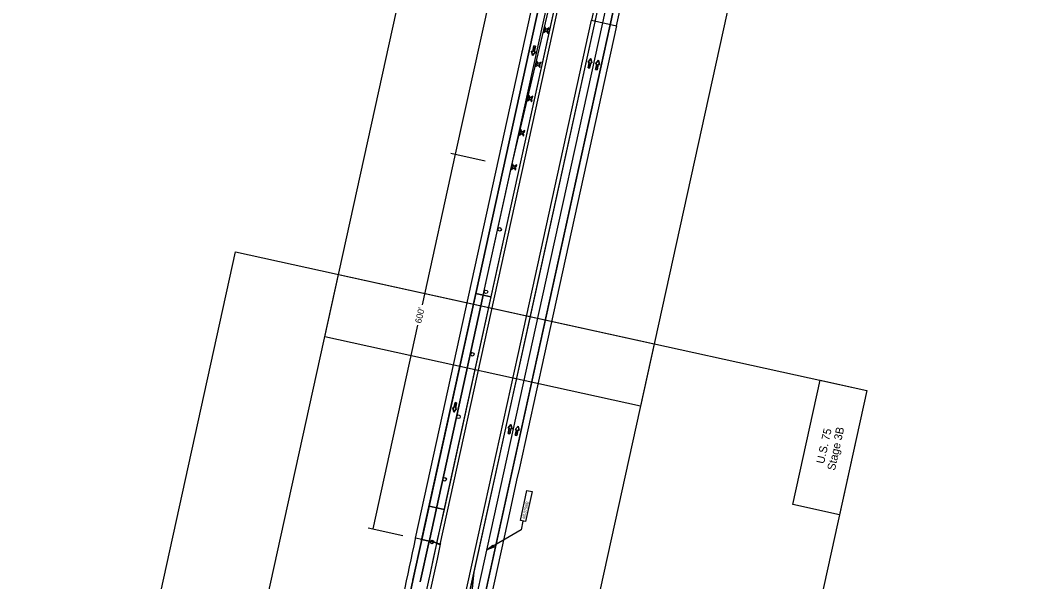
# Model space of a CAD drawing. Extents: x 14104283 to 14121738, y 8635219 to 8671666.
# Drawn here: x 14107490 to 14109077, y 8640895 to 8641773 of the extents above; entities that cross this region are included whole.
import ezdxf

# ---------------------------------------------------------------- set-up
doc = ezdxf.new("R2010")
doc.units = 0
for name, color, linetype in [('Cell', 7, 'Continuous'), ('Default', 7, 'Continuous'), ('dsnNonPlotable', 7, 'Continuous'), ('dsnPaintExistingBrokenLaneLineWhite', 7, 'Continuous'), ('dsnPaintExistingEdgeLineLeftYellow', 7, 'Continuous'), ('dsnPaintExistingEdgeLineRightWhite', 7, 'Continuous'), ('dsnPaintPlaceEdgeLineLeftYellow', 7, 'Continuous'), ('dsnStdLabel', 7, 'Continuous'), ('dsnStgShadingPrevPav', 7, 'Continuous'), ('dsnTapeExistingChannelizingLaneYellow', 7, 'Continuous'), ('dsnTapeRemoveChannelizingYellow', 7, 'Continuous'), ('dsnTextOverlapOdd', 7, 'Continuous'), ('Text', 7, 'Continuous')]:
    doc.layers.add(name, color=color, linetype=linetype)

msp = doc.modelspace()

# ---------------------------------------------------------------- linework, layer by layer
at = {"layer": 'Cell'}
for p, q in [((14108311.3, 8641758.1), (14108308.7, 8641756.9)), ((14108310.2, 8641763), (14108309.6, 8641760.3)), ((14108309.6, 8641760.3), (14108311.3, 8641758.1)), ((14108312.7, 8641758.9), (14108310.2, 8641763)), ((14108316.8, 8641761.4), (14108312.7, 8641758.9)), ((14108313.5, 8641757.6), (14108316.1, 8641758.7)), ((14108315.3, 8641755.3), (14108313.5, 8641757.6)), ((14108316.1, 8641758.7), (14108316.8, 8641761.4)), ((14108308.7, 8641756.9), (14108308.1, 8641754.3)), ((14108308.1, 8641754.3), (14108312.2, 8641756.7)), ((14108312.2, 8641756.7), (14108314.7, 8641752.7)), ((14108314.7, 8641752.7), (14108315.3, 8641755.3)), ((14108297.6, 8641709.5), (14108296.9, 8641706.8)), ((14108300.1, 8641705.4), (14108297.6, 8641709.5)), ((14108296.1, 8641703.4), (14108295.5, 8641700.7)), ((14108295.5, 8641700.7), (14108299.5, 8641703.2)), ((14108298.7, 8641704.6), (14108296.1, 8641703.4)), ((14108296.9, 8641706.8), (14108298.7, 8641704.6)), ((14108299.5, 8641703.2), (14108302, 8641699.1)), ((14108304.1, 8641707.9), (14108300.1, 8641705.4)), ((14108300.9, 8641704), (14108303.5, 8641705.2)), ((14108302.7, 8641701.8), (14108300.9, 8641704)), ((14108302, 8641699.1), (14108302.7, 8641701.8)), ((14108303.5, 8641705.2), (14108304.1, 8641707.9)), ((14108283.5, 8641649.9), (14108282.8, 8641647.2)), ((14108282.8, 8641647.2), (14108286.9, 8641649.7)), ((14108286.1, 8641651), (14108283.5, 8641649.9)), ((14108284.9, 8641655.9), (14108284.3, 8641653.3)), ((14108284.3, 8641653.3), (14108286.1, 8641651)), ((14108287.4, 8641651.9), (14108284.9, 8641655.9)), ((14108286.9, 8641649.7), (14108289.4, 8641645.6)), ((14108291.5, 8641654.4), (14108287.4, 8641651.9)), ((14108288.3, 8641650.5), (14108290.9, 8641651.7)), ((14108290, 8641648.3), (14108288.3, 8641650.5)), ((14108289.4, 8641645.6), (14108290, 8641648.3)), ((14108290.9, 8641651.7), (14108291.5, 8641654.4)), ((14108272.3, 8641602.4), (14108271.7, 8641599.7)), ((14108271.7, 8641599.7), (14108273.4, 8641597.5)), ((14108274.8, 8641598.3), (14108272.3, 8641602.4)), ((14108278.9, 8641600.8), (14108274.8, 8641598.3)), ((14108278.2, 8641598.2), (14108278.9, 8641600.8)), ((14108270.8, 8641596.3), (14108270.2, 8641593.7)), ((14108270.2, 8641593.7), (14108274.3, 8641596.2)), ((14108273.4, 8641597.5), (14108270.8, 8641596.3)), ((14108274.3, 8641596.2), (14108276.7, 8641592.1)), ((14108275.6, 8641597), (14108278.2, 8641598.2)), ((14108277.4, 8641594.8), (14108275.6, 8641597)), ((14108276.7, 8641592.1), (14108277.4, 8641594.8)), ((14108258.2, 8641542.8), (14108257.5, 8641540.1)), ((14108257.5, 8641540.1), (14108261.6, 8641542.6)), ((14108260.8, 8641544), (14108258.2, 8641542.8)), ((14108259.7, 8641548.9), (14108259, 8641546.2)), ((14108259, 8641546.2), (14108260.8, 8641544)), ((14108262.2, 8641544.8), (14108259.7, 8641548.9)), ((14108261.6, 8641542.6), (14108264.1, 8641538.6)), ((14108266.2, 8641547.3), (14108262.2, 8641544.8)), ((14108263, 8641543.5), (14108265.6, 8641544.6)), ((14108264.8, 8641541.2), (14108263, 8641543.5)), ((14108264.1, 8641538.6), (14108264.8, 8641541.2)), ((14108265.6, 8641544.6), (14108266.2, 8641547.3))]:
    msp.add_line(p, q, dxfattribs=at)
for points in [[(14108293, 8641733.2), (14108295.4, 8641732.6), (14108293.6, 8641724.1), (14108295.4, 8641723.7), (14108291, 8641718.2), (14108289.3, 8641725), (14108291.1, 8641724.6)], [(14108380, 8641698.3), (14108377.6, 8641698.8), (14108379.4, 8641707.3), (14108377.6, 8641707.7), (14108382, 8641713.2), (14108383.7, 8641706.4), (14108381.9, 8641706.8)], [(14108391.7, 8641695.7), (14108389.2, 8641696.2), (14108391.1, 8641704.8), (14108389.3, 8641705.2), (14108393.7, 8641710.6), (14108395.4, 8641703.9), (14108393.5, 8641704.3)], [(14108169.8, 8641175.5), (14108172.2, 8641175), (14108170.3, 8641166.4), (14108172.2, 8641166), (14108167.8, 8641160.6), (14108166.1, 8641167.4), (14108167.9, 8641167)], [(14108255.1, 8641126.4), (14108252.6, 8641126.9), (14108254.5, 8641135.4), (14108252.7, 8641135.8), (14108257, 8641141.3), (14108258.8, 8641134.5), (14108256.9, 8641134.9)], [(14108266.2, 8641123.9), (14108263.7, 8641124.4), (14108265.6, 8641133), (14108263.8, 8641133.4), (14108268.2, 8641138.8), (14108269.9, 8641132.1), (14108268, 8641132.5)]]:
    msp.add_lwpolyline(points, close=True, dxfattribs=at)
for points in [[(14108291.1, 8641724.6), (14108289.3, 8641725), (14108291, 8641718.2), (14108295.4, 8641723.7), (14108293.6, 8641724.1), (14108295.4, 8641732.6), (14108293, 8641733.2), (14108291.1, 8641724.6)], [(14108381.9, 8641706.8), (14108383.7, 8641706.4), (14108382, 8641713.2), (14108377.6, 8641707.7), (14108379.4, 8641707.3), (14108377.6, 8641698.8), (14108380, 8641698.3), (14108381.9, 8641706.8)], [(14108393.5, 8641704.3), (14108395.4, 8641703.9), (14108393.7, 8641710.6), (14108389.3, 8641705.2), (14108391.1, 8641704.8), (14108389.2, 8641696.2), (14108391.7, 8641695.7), (14108393.5, 8641704.3)], [(14108167.9, 8641167), (14108166.1, 8641167.4), (14108167.8, 8641160.6), (14108172.2, 8641166), (14108170.3, 8641166.4), (14108172.2, 8641175), (14108169.8, 8641175.5), (14108167.9, 8641167)], [(14108256.9, 8641134.9), (14108258.8, 8641134.5), (14108257, 8641141.3), (14108252.7, 8641135.8), (14108254.5, 8641135.4), (14108252.6, 8641126.9), (14108255.1, 8641126.4), (14108256.9, 8641134.9)], [(14108268, 8641132.5), (14108269.9, 8641132.1), (14108268.2, 8641138.8), (14108263.8, 8641133.4), (14108265.6, 8641133), (14108263.7, 8641124.4), (14108266.2, 8641123.9), (14108268, 8641132.5)]]:
    msp.add_lwpolyline(points, dxfattribs=at)
for centre in [(14108239.5, 8641446.3), (14108218, 8641348.6), (14108196.6, 8641251), (14108175.1, 8641153.3), (14108153.6, 8641055.6), (14108133.8, 8640957.6)]:
    msp.add_circle(centre, 2.75, dxfattribs=at)
at = {"layer": 'Default'}
for p, q in [((14108724, 8643185.7), (14108196.6, 8640785)), ((14108294.7, 8641343.2), (14108700.5, 8643190.9)), ((14108258, 8641544.6), (14108434.9, 8642294.1)), ((14108213.8, 8641343.5), (14108258, 8641544.6)), ((14108117.4, 8640960.3), (14108202.1, 8641346.1)), ((14108202.1, 8641346.1), (14108213.8, 8641343.5)), ((14108213.8, 8641343.5), (14108129.1, 8640957.7)), ((14108151.7, 8640692.6), (14108294.7, 8641343.2)), ((14108103.7, 8640898), (14108117.6, 8640961.2)), ((14108129.3, 8640958.6), (14108115.4, 8640895.4))]:
    msp.add_line(p, q, dxfattribs=at)
msp.add_lwpolyline([(14108976.3, 8644903.9), (14108611.6, 8643210.2), (14108202.1, 8641346.1)], dxfattribs=at)
msp.add_arc((14117394.1, 8638857.1), 9512, 167.61021, 171.32599, dxfattribs=at)
at = {"layer": 'dsnNonPlotable'}
for points in [[(14107966.2, 8641278.2), (14108302.6, 8642809.2), (14108795.9, 8642700.9), (14108459.5, 8641169.9)], [(14107490.5, 8639880.3), (14107826.8, 8641411.3), (14108813.3, 8641194.5), (14108476.9, 8639663.5)], [(14107651.3, 8639844.9), (14107987.7, 8641375.9), (14108480.9, 8641267.5), (14108144.5, 8639736.6)]]:
    msp.add_lwpolyline(points, close=True, dxfattribs=at)
at = {"layer": 'dsnPaintExistingBrokenLaneLineWhite'}
for p, q in [((14108213.8, 8641343.5), (14108623.3, 8643207.7)), ((14108129.1, 8640957.7), (14108213.8, 8641343.5)), ((14108189.8, 8640810.1), (14108306.4, 8641340.7)), ((14108115.4, 8640895.4), (14108129.3, 8640958.6))]:
    msp.add_line(p, q, dxfattribs=at)
msp.add_lwpolyline([(14108306.4, 8641340.7), (14108389, 8641717), (14108712.3, 8643188.3), (14108894.6, 8644035.3), (14109077, 8644882.2)], dxfattribs=at)
at = {"layer": 'dsnPaintExistingEdgeLineLeftYellow'}
msp.add_line((14108199.6, 8640910.3), (14108700.5, 8643190.8), dxfattribs=at)
at = {"layer": 'dsnPaintExistingEdgeLineRightWhite'}
for p, q in [((14108201.6, 8640807.6), (14108724, 8643185.7)), ((14108202.1, 8641346.1), (14108117.6, 8640961.2)), ((14108117.6, 8640961.2), (14108103.7, 8640898))]:
    msp.add_line(p, q, dxfattribs=at)
msp.add_lwpolyline([(14108976.3, 8644903.9), (14108611.6, 8643210.2), (14108202.1, 8641346.1)], dxfattribs=at)
msp.add_arc((14117394.1, 8638857.1), 9512, 167.61021, 168.00312, dxfattribs=at)
at = {"layer": 'dsnPaintPlaceEdgeLineLeftYellow'}
msp.add_line((14108151.7, 8640692.6), (14108199.6, 8640910.3), dxfattribs=at)
at = {"layer": 'dsnStdLabel'}
for p, q in [((14108249.1, 8641923.7), (14108170.1, 8641563.9)), ((14108170.1, 8641563.9), (14108118.4, 8641328.3)), ((14108162.9, 8641565.5), (14108217, 8641553.6)), ((14108111.3, 8641296.3), (14108041.4, 8640977.9)), ((14108034.1, 8640979.5), (14108088.3, 8640967.6))]:
    msp.add_line(p, q, dxfattribs=at)
at = {"layer": 'dsnStgShadingPrevPav'}
for p, q in [((14108107.8, 8640963.3), (14108601.8, 8643212.3)), ((14108611.6, 8643210.2), (14108117.6, 8640961.2)), ((14108694.7, 8643192.1), (14108383, 8641773.2)), ((14108422, 8641764.6), (14108733.8, 8643183.6)), ((14108383, 8641773.2), (14108422, 8641764.6)), ((14108225.5, 8641340.9), (14108202.1, 8641346.1)), ((14108107.8, 8640963.3), (14108107.6, 8640962.4)), ((14108117.6, 8640961.2), (14108107.8, 8640963.3)), ((14108117.6, 8640961.2), (14108107.8, 8640963.3)), ((14108117.4, 8640960.3), (14108117.6, 8640961.2)), ((14108140.8, 8640955.1), (14108141, 8640956)), ((14108140.8, 8640955.1), (14108146.7, 8640953.8)), ((14108141, 8640956), (14108146.9, 8640954.7)), ((14108146.9, 8640954.7), (14108146.7, 8640953.8))]:
    msp.add_line(p, q, dxfattribs=at)
for points in [[(14108999.8, 8644898.8), (14108817.4, 8644052), (14108635.1, 8643205.1), (14108387.9, 8642080.1), (14108140.8, 8640955.1)], [(14108202.1, 8641346.1), (14108611.6, 8643210.2), (14108976.3, 8644903.9)], [(14108999.8, 8644898.8), (14108635.1, 8643205.1), (14108225.5, 8641340.9)], [(14108146.7, 8640953.8), (14108640.9, 8643203.9), (14109005.6, 8644897.6)], [(14108117.4, 8640960.3), (14108117.6, 8640961.2), (14108141, 8640956), (14108140.8, 8640955.1)]]:
    msp.add_lwpolyline(points, dxfattribs=at)
for points in [[(14108081.5, 8640400.9), (14108123.3, 8640591.3), (14108126.6, 8640606), (14108216.7, 8641016.2), (14108268.2, 8641250.6), (14108383, 8641773.2), (14108422, 8641764.6), (14108309.4, 8641251.8), (14108270.2, 8641073.5), (14108265.9, 8641054), (14108255.7, 8641007.6), (14108202.1, 8640763.4), (14108120.6, 8640392.3)], [(14108129.1, 8641013.6), (14108202.1, 8641346.1), (14108225.5, 8641340.9), (14108152.5, 8641008.5)], [(14108141, 8640956), (14108117.6, 8640961.2), (14108129.1, 8641013.6), (14108152.5, 8641008.5)]]:
    msp.add_lwpolyline(points, close=True, dxfattribs=at)
for radius, end in [(9488, 172.22208), (9482, 172.22208), (9522, 168.68895), (9512, 168.32826), (9512, 168.32826), (9488, 168.32826)]:
    msp.add_arc((14117407.8, 8638919.4), radius, 167.61021, end, dxfattribs=at)
at = {"layer": 'dsnTapeExistingChannelizingLaneYellow'}
msp.add_line((14108258, 8641544.6), (14108434.9, 8642294.1), dxfattribs=at)
at = {"layer": 'dsnTapeRemoveChannelizingYellow'}
msp.add_line((14108189.8, 8640810.1), (14108199.6, 8640910.3), dxfattribs=at)
at = {"layer": 'dsnTextOverlapOdd'}
for points in [[(14108813.3, 8641194.5), (14108770.5, 8640999.9), (14108697.3, 8641016), (14108740.1, 8641210.6)], [(14108697.3, 8641016), (14108740.1, 8641210.6), (14108813.3, 8641194.5), (14108770.5, 8640999.9)]]:
    msp.add_lwpolyline(points, close=True, dxfattribs=at)
at = {"layer": 'Text'}
for points in [[(14108271.8, 8640991.2), (14108282.1, 8641038.2), (14108290.3, 8641036.4), (14108280, 8640989.4)], [(14108271.8, 8640991.2), (14108282.1, 8641038.2), (14108290.3, 8641036.4), (14108280, 8640989.4)], [(14108219.5, 8640945.1), (14108228.8, 8640952.6), (14108230.6, 8640949.5)]]:
    msp.add_lwpolyline(points, close=True, dxfattribs=at)
msp.add_lwpolyline([(14108275.9, 8640990.3), (14108272.8, 8640976.3), (14108219.5, 8640945.1)], dxfattribs=at)

# ---------------------------------------------------------------- texts
at = {"layer": 'dsnStdLabel'}
msp.add_text("600'", height=10, rotation=77.0531, dxfattribs=at).set_placement((14108116.8, 8641298.6))
at = {"layer": 'dsnTextOverlapOdd'}
for s, p in [('U.S. 75', (14108746.3, 8641079)), ('Stage 3B', (14108763.2, 8641068.6))]:
    msp.add_text(s, height=12.5, rotation=77.6078, dxfattribs=at).set_placement(p)
at = {"layer": 'Text'}
msp.add_text('ML075NB', height=4.48, rotation=77.6078, dxfattribs=at).set_placement((14108279, 8640993.5))

doc.saveas('drawing.dxf')
